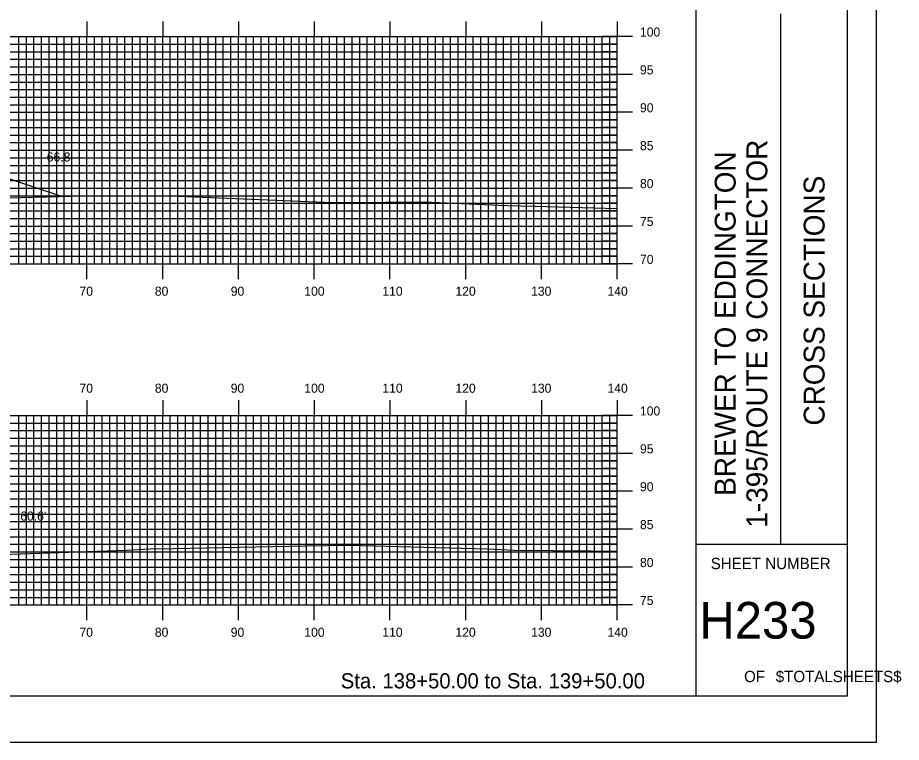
# Model space of a CAD drawing. Extents: x 1775957 to 1776301, y 442591 to 442811.
# Drawn here: x 1776184.1 to 1776300.7, y 442590.5 to 442686.2 of the extents above; entities that cross this region are included whole.
import ezdxf

# ---------------------------------------------------------------- set-up
doc = ezdxf.new("R2010")
doc.units = 0
for name, color, linetype in [('BORDER', 7, 'Continuous'), ('D_Roadway_Centerline', 7, 'Continuous'), ('D_Roadway_SlopeLines', 7, 'Continuous'), ('D_Text_Standard', 7, 'Continuous'), ('H_V ANNOTATION', 7, 'Continuous'), ('MAJOR', 7, 'Continuous'), ('MINOR', 7, 'Continuous'), ('PLOT BOUNDARY', 7, 'Continuous'), ('S_Roadway_Centerline', 7, 'Continuous')]:
    doc.layers.add(name, color=color, linetype=linetype)

msp = doc.modelspace()

# ---------------------------------------------------------------- linework, layer by layer
at = {"layer": 'BORDER'}
for p, q in [((1776273.62, 442596.67), (1776273.62, 442806.67)), ((1776284.81, 442616.67), (1776284.81, 442686.67)), ((1776273.62, 442616.67), (1776293.62, 442616.67))]:
    msp.add_line(p, q, dxfattribs=at)
msp.add_lwpolyline([(1775973.62, 442596.67), (1776293.62, 442596.67), (1776293.62, 442806.67), (1775973.62, 442806.67)], close=True, dxfattribs=at)
at = {"layer": 'D_Roadway_Centerline'}
msp.add_lwpolyline([(1776071.05, 442667.44), (1776086.85, 442672.71), (1776092.95, 442674.74), (1776100.22, 442677.16), (1776100.31, 442677.17), (1776103.22, 442677.28), (1776103.22, 442677.28), (1776103.23, 442677.28), (1776111.22, 442677.6), (1776123.22, 442677.84), (1776123.22, 442677.84), (1776129.1, 442677.73), (1776135.22, 442677.6), (1776135.22, 442677.6), (1776135.23, 442677.6), (1776143.23, 442677.28), (1776146.22, 442677.16), (1776146.23, 442677.16), (1776150.25, 442675.82), (1776153.5, 442674.74), (1776153.51, 442674.73), (1776190.01, 442662.57)], dxfattribs=at)
at = {"layer": 'D_Roadway_SlopeLines'}
msp.add_lwpolyline([(1776146.22, 442677.16), (1776190.01, 442662.57)], dxfattribs=at)
at = {"layer": 'MAJOR'}
for p, q in [((1776193.22, 442685.67), (1776193.22, 442683.67)), ((1776203.22, 442685.67), (1776203.22, 442683.67)), ((1776213.22, 442685.67), (1776213.22, 442683.67)), ((1776223.22, 442685.67), (1776223.22, 442683.67)), ((1776233.22, 442685.67), (1776233.22, 442683.67)), ((1776243.22, 442685.67), (1776243.22, 442683.67)), ((1776253.22, 442685.67), (1776253.22, 442683.67)), ((1776263.22, 442685.67), (1776263.22, 442683.67)), ((1775983.22, 442683.67), (1776263.22, 442683.67)), ((1775983.22, 442683.67), (1776263.22, 442683.67)), ((1776193.22, 442653.67), (1776193.22, 442683.67)), ((1776203.22, 442653.67), (1776203.22, 442683.67)), ((1776213.22, 442653.67), (1776213.22, 442683.67)), ((1776223.22, 442653.67), (1776223.22, 442683.67)), ((1776233.22, 442653.67), (1776233.22, 442683.67)), ((1776243.22, 442653.67), (1776243.22, 442683.67)), ((1776253.22, 442653.67), (1776253.22, 442683.67)), ((1776265.23, 442683.67), (1776261.22, 442683.67)), ((1776263.22, 442653.67), (1776263.22, 442683.67)), ((1776263.22, 442653.67), (1776263.22, 442683.67)), ((1775983.22, 442678.67), (1776263.22, 442678.67)), ((1776265.23, 442678.67), (1776261.22, 442678.67)), ((1775983.22, 442673.67), (1776263.22, 442673.67)), ((1776265.23, 442673.67), (1776261.22, 442673.67)), ((1775983.22, 442668.67), (1776263.22, 442668.67)), ((1776265.23, 442668.67), (1776261.22, 442668.67)), ((1775983.22, 442663.67), (1776263.22, 442663.67)), ((1776265.23, 442663.67), (1776261.22, 442663.67)), ((1775983.22, 442658.67), (1776263.22, 442658.67)), ((1776265.23, 442658.67), (1776261.22, 442658.67)), ((1775983.22, 442653.67), (1776263.22, 442653.67)), ((1775983.22, 442653.67), (1776263.22, 442653.67)), ((1776193.22, 442651.66), (1776193.22, 442653.67)), ((1776203.22, 442651.66), (1776203.22, 442653.67)), ((1776213.22, 442651.66), (1776213.22, 442653.67)), ((1776223.22, 442651.66), (1776223.22, 442653.67)), ((1776233.22, 442651.66), (1776233.22, 442653.67)), ((1776243.22, 442651.66), (1776243.22, 442653.67)), ((1776253.22, 442651.66), (1776253.22, 442653.67)), ((1776265.23, 442653.67), (1776261.22, 442653.67)), ((1776263.22, 442651.66), (1776263.22, 442653.67)), ((1776193.22, 442635.67), (1776193.22, 442633.67)), ((1776203.22, 442635.67), (1776203.22, 442633.67)), ((1776213.22, 442635.67), (1776213.22, 442633.67)), ((1776223.22, 442635.67), (1776223.22, 442633.67)), ((1776233.22, 442635.67), (1776233.22, 442633.67)), ((1776243.22, 442635.67), (1776243.22, 442633.67)), ((1776253.22, 442635.67), (1776253.22, 442633.67)), ((1776263.22, 442635.67), (1776263.22, 442633.67)), ((1775983.22, 442633.67), (1776263.22, 442633.67)), ((1775983.22, 442633.67), (1776263.22, 442633.67)), ((1776193.22, 442608.67), (1776193.22, 442633.67)), ((1776203.22, 442608.67), (1776203.22, 442633.67)), ((1776213.22, 442608.67), (1776213.22, 442633.67)), ((1776223.22, 442608.67), (1776223.22, 442633.67)), ((1776233.22, 442608.67), (1776233.22, 442633.67)), ((1776243.22, 442608.67), (1776243.22, 442633.67)), ((1776253.22, 442608.67), (1776253.22, 442633.67)), ((1776265.23, 442633.67), (1776261.22, 442633.67)), ((1776263.22, 442608.67), (1776263.22, 442633.67)), ((1776263.22, 442608.67), (1776263.22, 442633.67)), ((1775983.22, 442628.67), (1776263.22, 442628.67)), ((1776265.23, 442628.67), (1776261.22, 442628.67)), ((1775983.22, 442623.67), (1776263.22, 442623.67)), ((1776265.23, 442623.67), (1776261.22, 442623.67)), ((1775983.22, 442618.67), (1776263.22, 442618.67)), ((1776265.23, 442618.67), (1776261.22, 442618.67)), ((1775983.22, 442613.67), (1776263.22, 442613.67)), ((1776265.23, 442613.67), (1776261.22, 442613.67)), ((1775983.22, 442608.67), (1776263.22, 442608.67)), ((1775983.22, 442608.67), (1776263.22, 442608.67)), ((1776193.22, 442606.66), (1776193.22, 442608.67)), ((1776203.22, 442606.66), (1776203.22, 442608.67)), ((1776213.22, 442606.66), (1776213.22, 442608.67)), ((1776223.22, 442606.66), (1776223.22, 442608.67)), ((1776233.22, 442606.66), (1776233.22, 442608.67)), ((1776243.22, 442606.66), (1776243.22, 442608.67)), ((1776253.22, 442606.66), (1776253.22, 442608.67)), ((1776265.23, 442608.67), (1776261.22, 442608.67)), ((1776263.22, 442606.66), (1776263.22, 442608.67))]:
    msp.add_line(p, q, dxfattribs=at)
at = {"layer": 'MINOR'}
for p, q in [((1776184.22, 442653.67), (1776184.22, 442683.67)), ((1776185.22, 442653.67), (1776185.22, 442683.67)), ((1776186.22, 442653.67), (1776186.22, 442683.67)), ((1776187.22, 442653.67), (1776187.22, 442683.67)), ((1776188.22, 442653.67), (1776188.22, 442683.67)), ((1776189.22, 442653.67), (1776189.22, 442683.67)), ((1776190.22, 442653.67), (1776190.22, 442683.67)), ((1776191.22, 442653.67), (1776191.22, 442683.67)), ((1776192.22, 442653.67), (1776192.22, 442683.67)), ((1776194.22, 442653.67), (1776194.22, 442683.67)), ((1776195.22, 442653.67), (1776195.22, 442683.67)), ((1776196.22, 442653.67), (1776196.22, 442683.67)), ((1776197.22, 442653.67), (1776197.22, 442683.67)), ((1776198.22, 442653.67), (1776198.22, 442683.67)), ((1776199.22, 442653.67), (1776199.22, 442683.67)), ((1776200.22, 442653.67), (1776200.22, 442683.67)), ((1776201.22, 442653.67), (1776201.22, 442683.67)), ((1776202.22, 442653.67), (1776202.22, 442683.67)), ((1776204.22, 442653.67), (1776204.22, 442683.67)), ((1776205.22, 442653.67), (1776205.22, 442683.67)), ((1776206.22, 442653.67), (1776206.22, 442683.67)), ((1776207.22, 442653.67), (1776207.22, 442683.67)), ((1776208.22, 442653.67), (1776208.22, 442683.67)), ((1776209.22, 442653.67), (1776209.22, 442683.67)), ((1776210.22, 442653.67), (1776210.22, 442683.67)), ((1776211.22, 442653.67), (1776211.22, 442683.67)), ((1776212.22, 442653.67), (1776212.22, 442683.67)), ((1776214.22, 442653.67), (1776214.22, 442683.67)), ((1776215.22, 442653.67), (1776215.22, 442683.67)), ((1776216.22, 442653.67), (1776216.22, 442683.67)), ((1776217.22, 442653.67), (1776217.22, 442683.67)), ((1776218.22, 442653.67), (1776218.22, 442683.67)), ((1776219.22, 442653.67), (1776219.22, 442683.67)), ((1776220.22, 442653.67), (1776220.22, 442683.67)), ((1776221.22, 442653.67), (1776221.22, 442683.67)), ((1776222.22, 442653.67), (1776222.22, 442683.67)), ((1776224.22, 442653.67), (1776224.22, 442683.67)), ((1776225.22, 442653.67), (1776225.22, 442683.67)), ((1776226.22, 442653.67), (1776226.22, 442683.67)), ((1776227.22, 442653.67), (1776227.22, 442683.67)), ((1776228.22, 442653.67), (1776228.22, 442683.67)), ((1776229.22, 442653.67), (1776229.22, 442683.67)), ((1776230.22, 442653.67), (1776230.22, 442683.67)), ((1776231.22, 442653.67), (1776231.22, 442683.67)), ((1776232.22, 442653.67), (1776232.22, 442683.67)), ((1776234.22, 442653.67), (1776234.22, 442683.67)), ((1776235.22, 442653.67), (1776235.22, 442683.67)), ((1776236.22, 442653.67), (1776236.22, 442683.67)), ((1776237.22, 442653.67), (1776237.22, 442683.67)), ((1776238.22, 442653.67), (1776238.22, 442683.67)), ((1776239.22, 442653.67), (1776239.22, 442683.67)), ((1776240.22, 442653.67), (1776240.22, 442683.67)), ((1776241.22, 442653.67), (1776241.22, 442683.67)), ((1776242.22, 442653.67), (1776242.22, 442683.67)), ((1776244.22, 442653.67), (1776244.22, 442683.67)), ((1776245.22, 442653.67), (1776245.22, 442683.67)), ((1776246.22, 442653.67), (1776246.22, 442683.67)), ((1776247.22, 442653.67), (1776247.22, 442683.67)), ((1776248.22, 442653.67), (1776248.22, 442683.67)), ((1776249.22, 442653.67), (1776249.22, 442683.67)), ((1776250.22, 442653.67), (1776250.22, 442683.67)), ((1776251.22, 442653.67), (1776251.22, 442683.67)), ((1776252.22, 442653.67), (1776252.22, 442683.67)), ((1776254.22, 442653.67), (1776254.22, 442683.67)), ((1776255.22, 442653.67), (1776255.22, 442683.67)), ((1776256.22, 442653.67), (1776256.22, 442683.67)), ((1776257.22, 442653.67), (1776257.22, 442683.67)), ((1776258.22, 442653.67), (1776258.22, 442683.67)), ((1776259.22, 442653.67), (1776259.22, 442683.67)), ((1776260.22, 442653.67), (1776260.22, 442683.67)), ((1776261.22, 442653.67), (1776261.22, 442683.67)), ((1776262.22, 442653.67), (1776262.22, 442683.67)), ((1775983.22, 442682.67), (1776263.22, 442682.67)), ((1776263.22, 442682.67), (1776261.22, 442682.67)), ((1775983.22, 442681.67), (1776263.22, 442681.67)), ((1776263.22, 442681.67), (1776261.22, 442681.67)), ((1775983.22, 442680.67), (1776263.22, 442680.67)), ((1776263.22, 442680.67), (1776261.22, 442680.67)), ((1775983.22, 442679.67), (1776263.22, 442679.67)), ((1776263.22, 442679.67), (1776261.22, 442679.67)), ((1775983.22, 442677.67), (1776263.22, 442677.67)), ((1776263.22, 442677.67), (1776261.22, 442677.67)), ((1775983.22, 442676.67), (1776263.22, 442676.67)), ((1776263.22, 442676.67), (1776261.22, 442676.67)), ((1775983.22, 442675.67), (1776263.22, 442675.67)), ((1776263.22, 442675.67), (1776261.22, 442675.67)), ((1775983.22, 442674.67), (1776263.22, 442674.67)), ((1776263.22, 442674.67), (1776261.22, 442674.67)), ((1775983.22, 442672.67), (1776263.22, 442672.67)), ((1776263.22, 442672.67), (1776261.22, 442672.67)), ((1775983.22, 442671.67), (1776263.22, 442671.67)), ((1775983.22, 442670.67), (1776263.22, 442670.67)), ((1776263.22, 442671.67), (1776261.22, 442671.67)), ((1776263.22, 442670.67), (1776261.22, 442670.67)), ((1775983.22, 442669.67), (1776263.22, 442669.67)), ((1776263.22, 442669.67), (1776261.22, 442669.67)), ((1775983.22, 442667.67), (1776263.22, 442667.67)), ((1776263.22, 442667.67), (1776261.22, 442667.67)), ((1775983.22, 442666.67), (1776263.22, 442666.67)), ((1776263.22, 442666.67), (1776261.22, 442666.67)), ((1775983.22, 442665.67), (1776263.22, 442665.67)), ((1776263.22, 442665.67), (1776261.22, 442665.67)), ((1775983.22, 442664.67), (1776263.22, 442664.67)), ((1776263.22, 442664.67), (1776261.22, 442664.67)), ((1775983.22, 442662.67), (1776263.22, 442662.67)), ((1776263.22, 442662.67), (1776261.22, 442662.67)), ((1775983.22, 442661.67), (1776263.22, 442661.67)), ((1776263.22, 442661.67), (1776261.22, 442661.67)), ((1775983.22, 442660.67), (1776263.22, 442660.67)), ((1776263.22, 442660.67), (1776261.22, 442660.67)), ((1775983.22, 442659.67), (1776263.22, 442659.67)), ((1776263.22, 442659.67), (1776261.22, 442659.67)), ((1775983.22, 442657.67), (1776263.22, 442657.67)), ((1775983.22, 442656.67), (1776263.22, 442656.67)), ((1776263.22, 442657.67), (1776261.22, 442657.67)), ((1776263.22, 442656.67), (1776261.22, 442656.67)), ((1775983.22, 442655.67), (1776263.22, 442655.67)), ((1776263.22, 442655.67), (1776261.22, 442655.67)), ((1775983.22, 442654.67), (1776263.22, 442654.67)), ((1776263.22, 442654.67), (1776261.22, 442654.67)), ((1776184.22, 442608.67), (1776184.22, 442633.67)), ((1776185.22, 442608.67), (1776185.22, 442633.67)), ((1776186.22, 442608.67), (1776186.22, 442633.67)), ((1776187.22, 442608.67), (1776187.22, 442633.67)), ((1776188.22, 442608.67), (1776188.22, 442633.67)), ((1776189.22, 442608.67), (1776189.22, 442633.67)), ((1776190.22, 442608.67), (1776190.22, 442633.67)), ((1776191.22, 442608.67), (1776191.22, 442633.67)), ((1776192.22, 442608.67), (1776192.22, 442633.67)), ((1776194.22, 442608.67), (1776194.22, 442633.67)), ((1776195.22, 442608.67), (1776195.22, 442633.67)), ((1776196.22, 442608.67), (1776196.22, 442633.67)), ((1776197.22, 442608.67), (1776197.22, 442633.67)), ((1776198.22, 442608.67), (1776198.22, 442633.67)), ((1776199.22, 442608.67), (1776199.22, 442633.67)), ((1776200.22, 442608.67), (1776200.22, 442633.67)), ((1776201.22, 442608.67), (1776201.22, 442633.67)), ((1776202.22, 442608.67), (1776202.22, 442633.67)), ((1776204.22, 442608.67), (1776204.22, 442633.67)), ((1776205.22, 442608.67), (1776205.22, 442633.67)), ((1776206.22, 442608.67), (1776206.22, 442633.67)), ((1776207.22, 442608.67), (1776207.22, 442633.67)), ((1776208.22, 442608.67), (1776208.22, 442633.67)), ((1776209.22, 442608.67), (1776209.22, 442633.67)), ((1776210.22, 442608.67), (1776210.22, 442633.67)), ((1776211.22, 442608.67), (1776211.22, 442633.67)), ((1776212.22, 442608.67), (1776212.22, 442633.67)), ((1776214.22, 442608.67), (1776214.22, 442633.67)), ((1776215.22, 442608.67), (1776215.22, 442633.67)), ((1776216.22, 442608.67), (1776216.22, 442633.67)), ((1776217.22, 442608.67), (1776217.22, 442633.67)), ((1776218.22, 442608.67), (1776218.22, 442633.67)), ((1776219.22, 442608.67), (1776219.22, 442633.67)), ((1776220.22, 442608.67), (1776220.22, 442633.67)), ((1776221.22, 442608.67), (1776221.22, 442633.67)), ((1776222.22, 442608.67), (1776222.22, 442633.67)), ((1776224.22, 442608.67), (1776224.22, 442633.67)), ((1776225.22, 442608.67), (1776225.22, 442633.67)), ((1776226.22, 442608.67), (1776226.22, 442633.67)), ((1776227.22, 442608.67), (1776227.22, 442633.67)), ((1776228.22, 442608.67), (1776228.22, 442633.67)), ((1776229.22, 442608.67), (1776229.22, 442633.67)), ((1776230.22, 442608.67), (1776230.22, 442633.67)), ((1776231.22, 442608.67), (1776231.22, 442633.67)), ((1776232.22, 442608.67), (1776232.22, 442633.67)), ((1776234.22, 442608.67), (1776234.22, 442633.67)), ((1776235.22, 442608.67), (1776235.22, 442633.67)), ((1776236.22, 442608.67), (1776236.22, 442633.67)), ((1776237.22, 442608.67), (1776237.22, 442633.67)), ((1776238.22, 442608.67), (1776238.22, 442633.67)), ((1776239.22, 442608.67), (1776239.22, 442633.67)), ((1776240.22, 442608.67), (1776240.22, 442633.67)), ((1776241.22, 442608.67), (1776241.22, 442633.67)), ((1776242.22, 442608.67), (1776242.22, 442633.67)), ((1776244.22, 442608.67), (1776244.22, 442633.67)), ((1776245.22, 442608.67), (1776245.22, 442633.67)), ((1776246.22, 442608.67), (1776246.22, 442633.67)), ((1776247.22, 442608.67), (1776247.22, 442633.67)), ((1776248.22, 442608.67), (1776248.22, 442633.67)), ((1776249.22, 442608.67), (1776249.22, 442633.67)), ((1776250.22, 442608.67), (1776250.22, 442633.67)), ((1776251.22, 442608.67), (1776251.22, 442633.67)), ((1776252.22, 442608.67), (1776252.22, 442633.67)), ((1776254.22, 442608.67), (1776254.22, 442633.67)), ((1776255.22, 442608.67), (1776255.22, 442633.67)), ((1776256.22, 442608.67), (1776256.22, 442633.67)), ((1776257.22, 442608.67), (1776257.22, 442633.67)), ((1776258.22, 442608.67), (1776258.22, 442633.67)), ((1776259.22, 442608.67), (1776259.22, 442633.67)), ((1776260.22, 442608.67), (1776260.22, 442633.67)), ((1776261.22, 442608.67), (1776261.22, 442633.67)), ((1776262.22, 442608.67), (1776262.22, 442633.67)), ((1775983.22, 442632.67), (1776263.22, 442632.67)), ((1776263.22, 442632.67), (1776261.22, 442632.67)), ((1775983.22, 442631.67), (1776263.22, 442631.67)), ((1776263.22, 442631.67), (1776261.22, 442631.67)), ((1775983.22, 442630.67), (1776263.22, 442630.67)), ((1776263.22, 442630.67), (1776261.22, 442630.67)), ((1775983.22, 442629.67), (1776263.22, 442629.67)), ((1776263.22, 442629.67), (1776261.22, 442629.67)), ((1775983.22, 442627.67), (1776263.22, 442627.67)), ((1776263.22, 442627.67), (1776261.22, 442627.67)), ((1775983.22, 442626.67), (1776263.22, 442626.67)), ((1776263.22, 442626.67), (1776261.22, 442626.67)), ((1775983.22, 442625.67), (1776263.22, 442625.67)), ((1776263.22, 442625.67), (1776261.22, 442625.67)), ((1775983.22, 442624.67), (1776263.22, 442624.67)), ((1776263.22, 442624.67), (1776261.22, 442624.67)), ((1775983.22, 442622.67), (1776263.22, 442622.67)), ((1775983.22, 442621.67), (1776263.22, 442621.67)), ((1776263.22, 442622.67), (1776261.22, 442622.67)), ((1776263.22, 442621.67), (1776261.22, 442621.67)), ((1775983.22, 442620.67), (1776263.22, 442620.67)), ((1776263.22, 442620.67), (1776261.22, 442620.67)), ((1775983.22, 442619.67), (1776263.22, 442619.67)), ((1776263.22, 442619.67), (1776261.22, 442619.67)), ((1775983.22, 442617.67), (1776263.22, 442617.67)), ((1776263.22, 442617.67), (1776261.22, 442617.67)), ((1775983.22, 442616.67), (1776263.22, 442616.67)), ((1776263.22, 442616.67), (1776261.22, 442616.67)), ((1775983.22, 442615.67), (1776263.22, 442615.67)), ((1775983.22, 442614.67), (1776263.22, 442614.67)), ((1776263.22, 442615.67), (1776261.22, 442615.67)), ((1776263.22, 442614.67), (1776261.22, 442614.67)), ((1775983.22, 442612.67), (1776263.22, 442612.67)), ((1776263.22, 442612.67), (1776261.22, 442612.67)), ((1775983.22, 442611.67), (1776263.22, 442611.67)), ((1776263.22, 442611.67), (1776261.22, 442611.67)), ((1775983.22, 442610.67), (1776263.22, 442610.67)), ((1776263.22, 442610.67), (1776261.22, 442610.67)), ((1775983.22, 442609.67), (1776263.22, 442609.67)), ((1776263.22, 442609.67), (1776261.22, 442609.67))]:
    msp.add_line(p, q, dxfattribs=at)
at = {"layer": 'PLOT BOUNDARY'}
msp.add_lwpolyline([(1775957.44, 442590.55), (1776297.44, 442590.55), (1776297.44, 442810.55), (1775957.44, 442810.55)], close=True, dxfattribs=at)
at = {"layer": 'S_Roadway_Centerline'}
for points in [[(1776179.48, 442662.29), (1776191.24, 442662.6), (1776201.13, 442662.71), (1776204.26, 442662.65), (1776224.59, 442661.81), (1776227.5, 442661.76), (1776237.75, 442661.88), (1776248.7, 442661.39), (1776252.37, 442661.28), (1776263.22, 442660.99)], [(1776181.88, 442615.33), (1776198.43, 442615.92), (1776201.57, 442616.08), (1776204.65, 442616.12), (1776222.08, 442616.48), (1776227.73, 442616.54), (1776246.05, 442616.07), (1776249.66, 442615.92), (1776259.79, 442615.8), (1776263.22, 442615.78)]]:
    msp.add_lwpolyline(points, dxfattribs=at)

# ---------------------------------------------------------------- texts
at = {"layer": 'BORDER'}
for s, p in [('1-395/ROUTE 9 CONNECTOR', (1776283.03, 442618.87)), ('BREWER TO EDDINGTON', (1776278.85, 442623.07)), ('CROSS SECTIONS', (1776290.59, 442632.34))]:
    msp.add_text(s, height=2.7557, rotation=90, dxfattribs=at).set_placement(p)
for s, height, p in [('SHEET NUMBER', 1.4905, (1776275.56, 442613.4)), ('H233', 4.839, (1776274.06, 442604.23)), ('OF', 1.491, (1776279.96, 442598.49)), ('$TOTALSHEETS$', 1.4905, (1776284.14, 442598.49))]:
    msp.add_text(s, height=height, dxfattribs=at).set_placement(p)
at = {"layer": 'D_Text_Standard'}
for s, p in [("66.8'", (1776187.91, 442667.18)), ("60.6'", (1776184.41, 442619.8))]:
    msp.add_text(s, height=1.2, dxfattribs=at).set_placement(p)
at = {"layer": 'H_V ANNOTATION'}
for s, height, p in [('100', 1.2, (1776266.22, 442683.67)), ('95', 1.2, (1776266.22, 442678.67)), ('90', 1.2, (1776266.22, 442673.67)), ('85', 1.2, (1776266.22, 442668.67)), ('80', 1.2, (1776266.22, 442663.67)), ('75', 1.2, (1776266.22, 442658.67)), ('70', 1.2, (1776266.22, 442653.67)), ('70', 1.2, (1776192.23, 442649.47)), ('80', 1.2, (1776202.18, 442649.47)), ('90', 1.2, (1776212.2, 442649.47)), ('100', 1.2, (1776221.91, 442649.47)), ('110', 1.2, (1776232.21, 442649.47)), ('120', 1.2, (1776241.86, 442649.47)), ('130', 1.2, (1776251.85, 442649.47)), ('140', 1.2, (1776261.93, 442649.47)), ('70', 1.2, (1776192.23, 442636.67)), ('80', 1.2, (1776202.18, 442636.67)), ('90', 1.2, (1776212.2, 442636.67)), ('100', 1.2, (1776221.91, 442636.67)), ('110', 1.2, (1776232.21, 442636.67)), ('120', 1.2, (1776241.86, 442636.67)), ('130', 1.2, (1776251.85, 442636.67)), ('140', 1.2, (1776261.93, 442636.67)), ('100', 1.2, (1776266.22, 442633.67)), ('95', 1.2, (1776266.22, 442628.67)), ('90', 1.2, (1776266.22, 442623.67)), ('85', 1.2, (1776266.22, 442618.67)), ('80', 1.2, (1776266.22, 442613.67)), ('75', 1.2, (1776266.22, 442608.67)), ('70', 1.2, (1776192.23, 442604.47)), ('80', 1.2, (1776202.18, 442604.47)), ('90', 1.2, (1776212.2, 442604.47)), ('100', 1.2, (1776221.91, 442604.47)), ('110', 1.2, (1776232.21, 442604.47)), ('120', 1.2, (1776241.86, 442604.47)), ('130', 1.2, (1776251.85, 442604.47)), ('140', 1.2, (1776261.93, 442604.47)), ('Sta. 138+50.00 to Sta. 139+50.00', 2.0004, (1776226.72, 442597.66))]:
    msp.add_text(s, height=height, dxfattribs=at).set_placement(p)

doc.saveas('drawing.dxf')
